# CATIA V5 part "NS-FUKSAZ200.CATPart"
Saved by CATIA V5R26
Part number: NS-FUKSAZ200
Bounding box of the stored display mesh (mm): x -120.601 to 120.601, y -249.867 to 0, z -57.2 to 55.6
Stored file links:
  R:\Document\坂尻\その他\ナベヤデータ変換\安全カバーキャスター\MCBKSAZ200\NS-FUKSAZ200.CATPart
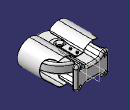
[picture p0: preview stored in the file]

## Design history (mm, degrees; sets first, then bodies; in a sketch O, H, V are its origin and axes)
Body1 (main body)
  Solid1: solid without history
